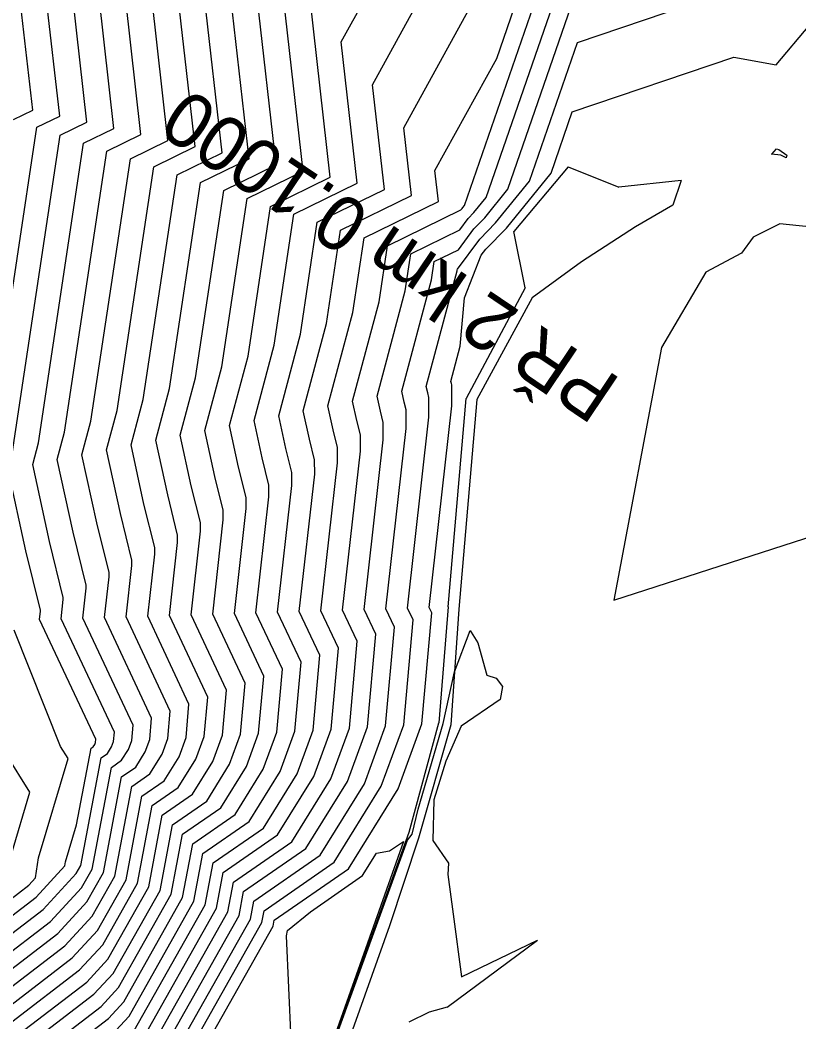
# Model space of a CAD drawing. Extents: x -549394 to -546608, y -1037055 to -1033629.
# Drawn here: x -547627.3 to -547498.3, y -1035691 to -1035525.2 of the extents above; entities that cross this region are included whole.
import ezdxf

# ---------------------------------------------------------------- set-up
doc = ezdxf.new("R2010")
doc.units = 0
for name, color, linetype in [('hlavni_vrst', 7, 'Continuous'), ('hrana_L', 7, 'Continuous'), ('norm_vrst', 7, 'Continuous'), ('x_popis_pricne_rezy_C11', 7, 'Continuous')]:
    doc.layers.add(name, color=color, linetype=linetype)

msp = doc.modelspace()

# ---------------------------------------------------------------- linework, layer by layer
at = {"layer": 'hlavni_vrst'}
for p, q in [((-547574.09, -1035528.75), (-547531.7, -1035451.74)), ((-547616.21, -1035542.07), (-547625.05, -1035464.23)), ((-547593.82, -1035547.12), (-547599.94, -1035493.2)), ((-547550.08, -1035554.5), (-547533.27, -1035505.92)), ((-547571.43, -1035552.17), (-547574.09, -1035528.75)), ((-547620.62, -1035544.22), (-547616.21, -1035542.07)), ((-547628.56, -1035596.95), (-547620.62, -1035544.22)), ((-547601.27, -1035550.76), (-547593.82, -1035547.12)), ((-547606.88, -1035587.96), (-547601.27, -1035550.76)), ((-547581.93, -1035557.29), (-547571.43, -1035552.17)), ((-547552.14, -1035557.03), (-547550.08, -1035554.5)), ((-547585.19, -1035578.97), (-547581.93, -1035557.29)), ((-547553.1, -1035558.01), (-547552.14, -1035557.03)), ((-547554.48, -1035559.88), (-547553.1, -1035558.01)), ((-547562.58, -1035563.83), (-547554.48, -1035559.88)), ((-547563.51, -1035569.98), (-547562.58, -1035563.83)), ((-547568.15, -1035587.41), (-547563.51, -1035569.98)), ((-547588.52, -1035591.45), (-547585.19, -1035578.97)), ((-547608.88, -1035595.49), (-547606.88, -1035587.96)), ((-547567.61, -1035589.92), (-547568.15, -1035587.41)), ((-547567.15, -1035591.76), (-547567.61, -1035589.92)), ((-547587.18, -1035597.62), (-547588.52, -1035591.45)), ((-547567.14, -1035594.65), (-547567.15, -1035591.76)), ((-547570.29, -1035622.71), (-547567.14, -1035594.65)), ((-547606.75, -1035605.31), (-547608.88, -1035595.49)), ((-547586.06, -1035602.12), (-547587.18, -1035597.62)), ((-547626.32, -1035613.01), (-547629.25, -1035599.53)), ((-547586.06, -1035604.1), (-547586.06, -1035602.12)), ((-547604.98, -1035612.47), (-547606.75, -1035605.31)), ((-547588.21, -1035623.26), (-547586.06, -1035604.1)), ((-547623.89, -1035622.83), (-547626.32, -1035613.01)), ((-547606.13, -1035623.81), (-547604.97, -1035613.54)), ((-547604.97, -1035613.54), (-547604.98, -1035612.47)), ((-547624.04, -1035624.36), (-547623.89, -1035622.98)), ((-547623.89, -1035622.98), (-547623.89, -1035622.83)), ((-547583.84, -1035632.6), (-547588.21, -1035623.26)), ((-547568.38, -1035626.79), (-547570.29, -1035622.71)), ((-547614.75, -1035644.21), (-547624.04, -1035624.36)), ((-547599.3, -1035638.4), (-547606.13, -1035623.81)), ((-547569.74, -1035642.17), (-547568.38, -1035626.79)), ((-547584.76, -1035643.03), (-547583.84, -1035632.6)), ((-547599.78, -1035643.89), (-547599.3, -1035638.4)), ((-547587, -1035649.14), (-547584.76, -1035643.03)), ((-547573.04, -1035651.17), (-547569.74, -1035642.17)), ((-547615.15, -1035645.45), (-547614.91, -1035645.06)), ((-547614.91, -1035645.06), (-547614.8, -1035644.75)), ((-547614.8, -1035644.75), (-547614.75, -1035644.21)), ((-547600.95, -1035647.1), (-547599.78, -1035643.89)), ((-547617.92, -1035658.38), (-547615.51, -1035645.69)), ((-547615.51, -1035645.69), (-547615.15, -1035645.45)), ((-547603.42, -1035651.06), (-547600.95, -1035647.1)), ((-547591.68, -1035656.67), (-547587, -1035649.14)), ((-547607.09, -1035653.6), (-547603.42, -1035651.06)), ((-547579.94, -1035662.28), (-547573.04, -1035651.17)), ((-547609.72, -1035667.46), (-547607.09, -1035653.6)), ((-547598.67, -1035661.51), (-547591.68, -1035656.67)), ((-547619.73, -1035664.49), (-547617.92, -1035658.38)), ((-547600.36, -1035670.41), (-547598.67, -1035661.51)), ((-547590.25, -1035669.42), (-547579.94, -1035662.28)), ((-547619.83, -1035665.15), (-547619.73, -1035664.49)), ((-547624.63, -1035670.35), (-547619.83, -1035665.15)), ((-547614.46, -1035675.87), (-547609.72, -1035667.46)), ((-547591, -1035673.37), (-547590.25, -1035669.42)), ((-547641.51, -1035683.3), (-547624.63, -1035670.35)), ((-547610.1, -1035687.67), (-547600.36, -1035670.41)), ((-547605.74, -1035699.48), (-547591, -1035673.37)), ((-547618.63, -1035680.39), (-547614.46, -1035675.87)), ((-547630.77, -1035689.69), (-547618.63, -1035680.39)), ((-547612.64, -1035690.42), (-547610.1, -1035687.67)), ((-547620.02, -1035696.08), (-547612.64, -1035690.42))]:
    msp.add_line(p, q, dxfattribs=at)
at = {"layer": 'hrana_L'}
for p, q in [((-547536.52, -1035549.43), (-547545.54, -1035560.15)), ((-547536.52, -1035549.43), (-547528.16, -1035552.81)), ((-547517.84, -1035551.7), (-547528.16, -1035552.81)), ((-547517.84, -1035551.7), (-547519.2, -1035555.78)), ((-547519.2, -1035555.78), (-547525.37, -1035559.4)), ((-547543.62, -1035569.46), (-547545.54, -1035560.15)), ((-547525.37, -1035559.4), (-547534.34, -1035565.16)), ((-547534.34, -1035565.16), (-547542.48, -1035571.14)), ((-547543.62, -1035569.46), (-547553.41, -1035587.8)), ((-547542.48, -1035571.14), (-547551.65, -1035587.97)), ((-547556.39, -1035622.28), (-547553.41, -1035587.8)), ((-547551.65, -1035587.97), (-547554.6, -1035622.69)), ((-547556.39, -1035622.28), (-547557.91, -1035641.49)), ((-547554.6, -1035622.69), (-547555.97, -1035641.83)), ((-547562.86, -1035659.58), (-547557.91, -1035641.49)), ((-547555.97, -1035641.83), (-547561.31, -1035660.56)), ((-547577.52, -1035700.25), (-547562.86, -1035659.58)), ((-547561.31, -1035660.56), (-547566.1, -1035675.11)), ((-547566.1, -1035675.11), (-547574.58, -1035698.92))]:
    msp.add_line(p, q, dxfattribs=at)
at = {"layer": 'norm_vrst'}
for p, q in [((-547611.73, -1035543.08), (-547620.63, -1035464.77)), ((-547607.25, -1035544.09), (-547615.45, -1035471.88)), ((-547620.69, -1035541.06), (-547628.31, -1035473.99)), ((-547568.92, -1035535.86), (-547534.38, -1035473.12)), ((-547602.78, -1035545.1), (-547610.28, -1035478.99)), ((-547625.17, -1035540.05), (-547631.56, -1035483.75)), ((-547548.36, -1035531.52), (-547531.56, -1035482.96)), ((-547598.3, -1035546.11), (-547605.11, -1035486.09)), ((-547553.66, -1035555.84), (-547532.42, -1035494.44)), ((-547589.34, -1035548.13), (-547594.77, -1035500.31)), ((-547563.74, -1035542.97), (-547541.37, -1035502.32)), ((-547584.86, -1035549.14), (-547589.6, -1035507.42)), ((-547580.38, -1035550.15), (-547584.43, -1035514.53)), ((-547546.5, -1035553.16), (-547534.13, -1035517.4)), ((-547534.99, -1035528.88), (-547500.11, -1035517.04)), ((-547575.91, -1035551.16), (-547579.26, -1035521.64)), ((-547502.11, -1035532.54), (-547496.51, -1035525.96)), ((-547542.92, -1035551.82), (-547534.99, -1035528.88)), ((-547558.57, -1035550.08), (-547548.36, -1035531.52)), ((-547535.84, -1035540.36), (-547509.07, -1035531.27)), ((-547509.07, -1035531.27), (-547502.11, -1035532.54)), ((-547566.95, -1035553.18), (-547568.92, -1035535.86)), ((-547628.35, -1035541.61), (-547625.17, -1035540.05)), ((-547539.35, -1035550.49), (-547535.84, -1035540.36)), ((-547624.49, -1035542.91), (-547620.69, -1035541.06)), ((-547632.9, -1035598.75), (-547624.49, -1035542.91)), ((-547616.75, -1035545.53), (-547611.73, -1035543.08)), ((-547562.47, -1035554.19), (-547563.74, -1035542.97)), ((-547624.22, -1035595.15), (-547616.75, -1035545.53)), ((-547612.88, -1035546.84), (-547607.25, -1035544.09)), ((-547609.01, -1035548.14), (-547602.78, -1035545.1)), ((-547619.89, -1035593.35), (-547612.88, -1035546.84)), ((-547605.14, -1035549.45), (-547598.3, -1035546.11)), ((-547502.83, -1035547.38), (-547502.79, -1035547.35)), ((-547502.79, -1035547.35), (-547502.01, -1035546.46)), ((-547502.01, -1035546.46), (-547501.63, -1035546.59)), ((-547501.63, -1035546.59), (-547500.34, -1035547.5)), ((-547615.55, -1035591.55), (-547609.01, -1035548.14)), ((-547597.4, -1035552.07), (-547589.34, -1035548.13)), ((-547501.29, -1035547.53), (-547502.83, -1035547.38)), ((-547500.43, -1035547.94), (-547501.29, -1035547.53)), ((-547500.34, -1035547.5), (-547500.43, -1035547.94)), ((-547611.21, -1035589.76), (-547605.14, -1035549.45)), ((-547593.53, -1035553.37), (-547584.86, -1035549.14)), ((-547589.66, -1035554.68), (-547580.38, -1035550.15)), ((-547557.99, -1035555.2), (-547558.57, -1035550.08)), ((-547546.75, -1035559.58), (-547539.35, -1035550.49)), ((-547602.54, -1035586.16), (-547597.4, -1035552.07)), ((-547585.8, -1035555.99), (-547575.91, -1035551.16)), ((-547548.54, -1035558.73), (-547542.92, -1035551.82)), ((-547598.2, -1035584.36), (-547593.53, -1035553.37)), ((-547578.06, -1035558.6), (-547566.95, -1035553.18)), ((-547550.34, -1035557.88), (-547546.5, -1035553.16)), ((-547593.87, -1035582.56), (-547589.66, -1035554.68)), ((-547574.19, -1035559.91), (-547562.47, -1035554.19)), ((-547570.32, -1035561.22), (-547557.99, -1035555.2)), ((-547589.53, -1035580.77), (-547585.8, -1035555.99)), ((-547566.45, -1035562.52), (-547554.27, -1035556.58)), ((-547554.27, -1035556.58), (-547554.07, -1035556.32)), ((-547554.07, -1035556.32), (-547553.94, -1035556.19)), ((-547553.94, -1035556.19), (-547553.66, -1035555.84)), ((-547580.85, -1035577.17), (-547578.06, -1035558.6)), ((-547552.13, -1035559.71), (-547550.34, -1035557.88)), ((-547551.16, -1035561.4), (-547548.54, -1035558.73)), ((-547501.49, -1035558.87), (-547505.88, -1035561.09)), ((-547492.29, -1035559.82), (-547501.49, -1035558.87)), ((-547576.52, -1035575.37), (-547574.19, -1035559.91)), ((-547554.7, -1035563.18), (-547552.13, -1035559.71)), ((-547550.18, -1035563.09), (-547546.75, -1035559.58)), ((-547572.18, -1035573.58), (-547570.32, -1035561.22)), ((-547554.84, -1035566.37), (-547551.16, -1035561.4)), ((-547505.88, -1035561.09), (-547507.85, -1035563.73)), ((-547567.84, -1035571.78), (-547566.45, -1035562.52)), ((-547558.71, -1035565.14), (-547554.7, -1035563.18)), ((-547550.9, -1035564.06), (-547550.18, -1035563.09)), ((-547507.85, -1035563.73), (-547513.72, -1035566.89)), ((-547559.17, -1035568.18), (-547558.71, -1035565.14)), ((-547553.7, -1035571.15), (-547550.9, -1035564.06)), ((-547560.01, -1035585.79), (-547554.91, -1035566.67)), ((-547554.91, -1035566.67), (-547554.9, -1035566.51)), ((-547554.9, -1035566.51), (-547554.84, -1035566.37)), ((-547513.72, -1035566.89), (-547521.05, -1035579.34)), ((-547564.08, -1035586.6), (-547559.17, -1035568.18)), ((-547572.22, -1035588.22), (-547567.84, -1035571.78)), ((-547554.38, -1035579.14), (-547553.7, -1035571.15)), ((-547576.3, -1035589.03), (-547572.18, -1035573.58)), ((-547580.37, -1035589.83), (-547576.52, -1035575.37)), ((-547584.44, -1035590.64), (-547580.85, -1035577.17)), ((-547555.93, -1035584.99), (-547554.38, -1035579.14)), ((-547521.05, -1035579.34), (-547528.95, -1035621.19)), ((-547592.59, -1035592.26), (-547589.53, -1035580.77)), ((-547596.66, -1035593.07), (-547593.87, -1035582.56)), ((-547600.74, -1035593.87), (-547598.2, -1035584.36)), ((-547555.86, -1035585.31), (-547555.93, -1035584.99)), ((-547555.8, -1035585.54), (-547555.86, -1035585.31)), ((-547604.81, -1035594.68), (-547602.54, -1035586.16)), ((-547563.69, -1035588.38), (-547564.08, -1035586.6)), ((-547559.78, -1035586.85), (-547560.01, -1035585.79)), ((-547559.59, -1035587.61), (-547559.78, -1035586.85)), ((-547555.79, -1035588.99), (-547555.8, -1035585.54)), ((-547571.52, -1035591.46), (-547572.22, -1035588.22)), ((-547563.37, -1035589.69), (-547563.69, -1035588.38)), ((-547559.58, -1035590.88), (-547559.59, -1035587.61)), ((-547612.96, -1035596.3), (-547611.21, -1035589.76)), ((-547579.35, -1035594.54), (-547580.37, -1035589.83)), ((-547575.43, -1035593), (-547576.3, -1035589.03)), ((-547563.36, -1035592.77), (-547563.37, -1035589.69)), ((-547559.54, -1035622.38), (-547555.79, -1035588.99)), ((-547617.03, -1035597.11), (-547615.55, -1035591.55)), ((-547583.26, -1035596.08), (-547584.44, -1035590.64)), ((-547570.93, -1035593.83), (-547571.52, -1035591.46)), ((-547563.13, -1035622.49), (-547559.58, -1035590.88)), ((-547621.1, -1035597.91), (-547619.89, -1035593.35)), ((-547595.01, -1035600.7), (-547596.66, -1035593.07)), ((-547591.09, -1035599.16), (-547592.59, -1035592.26)), ((-547574.72, -1035595.9), (-547575.43, -1035593)), ((-547566.71, -1035622.6), (-547563.36, -1035592.77)), ((-547625.18, -1035598.72), (-547624.22, -1035595.15)), ((-547602.83, -1035603.77), (-547604.81, -1035594.68)), ((-547598.92, -1035602.24), (-547600.74, -1035593.87)), ((-547578.5, -1035597.97), (-547579.35, -1035594.54)), ((-547570.93, -1035596.54), (-547570.93, -1035593.83)), ((-547614.58, -1035608.39), (-547617.03, -1035597.11)), ((-547610.66, -1035606.85), (-547612.96, -1035596.3)), ((-547582.28, -1035600.04), (-547583.26, -1035596.08)), ((-547574.71, -1035598.43), (-547574.72, -1035595.9)), ((-547573.88, -1035622.82), (-547570.93, -1035596.54)), ((-547622.41, -1035611.47), (-547625.18, -1035598.72)), ((-547618.49, -1035609.93), (-547621.1, -1035597.91)), ((-547578.49, -1035600.32), (-547578.5, -1035597.97)), ((-547577.46, -1035622.93), (-547574.71, -1035598.43)), ((-547589.85, -1035604.19), (-547591.09, -1035599.16)), ((-547582.28, -1035602.21), (-547582.28, -1035600.04)), ((-547581.04, -1035623.04), (-547578.49, -1035600.32)), ((-547593.63, -1035606.26), (-547595.01, -1035600.7)), ((-547597.41, -1035608.33), (-547598.92, -1035602.24)), ((-547584.63, -1035623.15), (-547582.28, -1035602.21)), ((-547601.19, -1035610.4), (-547602.83, -1035603.77)), ((-547589.84, -1035605.98), (-547589.85, -1035604.19)), ((-547608.76, -1035614.55), (-547610.66, -1035606.85)), ((-547593.62, -1035607.87), (-547593.63, -1035606.26)), ((-547591.79, -1035623.37), (-547589.84, -1035605.98)), ((-547612.54, -1035616.62), (-547614.58, -1035608.39)), ((-547597.41, -1035609.76), (-547597.41, -1035608.33)), ((-547595.38, -1035623.48), (-547593.62, -1035607.87)), ((-547616.32, -1035618.69), (-547618.49, -1035609.93)), ((-547598.96, -1035623.59), (-547597.41, -1035609.76)), ((-547620.11, -1035620.76), (-547622.41, -1035611.47)), ((-547602.54, -1035623.7), (-547601.19, -1035611.65)), ((-547601.19, -1035611.65), (-547601.19, -1035610.4)), ((-547528.95, -1035621.19), (-547495.64, -1035610.43)), ((-547608.76, -1035615.42), (-547608.76, -1035614.55)), ((-547612.54, -1035617.31), (-547612.54, -1035616.62)), ((-547609.71, -1035623.92), (-547608.76, -1035615.42)), ((-547613.29, -1035624.03), (-547612.54, -1035617.31)), ((-547616.88, -1035624.14), (-547616.32, -1035619.2)), ((-547616.32, -1035619.2), (-547616.32, -1035618.69)), ((-547620.46, -1035624.25), (-547620.11, -1035621.09)), ((-547620.11, -1035621.09), (-547620.11, -1035620.76)), ((-547593.11, -1035636.08), (-547598.96, -1035623.59)), ((-547590.02, -1035634.92), (-547595.38, -1035623.48)), ((-547586.93, -1035633.76), (-547591.79, -1035623.37)), ((-547580.75, -1035631.43), (-547584.63, -1035623.15)), ((-547577.66, -1035630.27), (-547581.04, -1035623.04)), ((-547574.57, -1035629.11), (-547577.46, -1035622.93)), ((-547571.47, -1035627.95), (-547573.88, -1035622.82)), ((-547565.29, -1035625.63), (-547566.71, -1035622.6)), ((-547562.2, -1035624.46), (-547563.13, -1035622.49)), ((-547560.73, -1035641.65), (-547559.11, -1035623.3)), ((-547559.11, -1035623.3), (-547559.54, -1035622.38)), ((-547611.66, -1035643.05), (-547620.46, -1035624.25)), ((-547608.57, -1035641.89), (-547616.88, -1035624.14)), ((-547605.48, -1035640.73), (-547613.29, -1035624.03)), ((-547602.39, -1035639.57), (-547609.71, -1035623.92)), ((-547596.2, -1035637.24), (-547602.54, -1035623.7)), ((-547563.74, -1035641.82), (-547562.2, -1035624.46)), ((-547620.57, -1035645.42), (-547628.26, -1035626.14)), ((-547566.74, -1035642), (-547565.29, -1035625.63)), ((-547555.34, -1035633.06), (-547552.77, -1035626.2)), ((-547552.77, -1035626.2), (-547552.59, -1035626.45)), ((-547552.59, -1035626.45), (-547551.46, -1035628.25)), ((-547572.75, -1035642.34), (-547571.47, -1035627.95)), ((-547551.46, -1035628.25), (-547550, -1035633.58)), ((-547578.75, -1035642.68), (-547577.66, -1035630.27)), ((-547575.75, -1035642.51), (-547574.57, -1035629.11)), ((-547581.76, -1035642.86), (-547580.75, -1035631.43)), ((-547557.23, -1035641.61), (-547555.34, -1035633.06)), ((-547550, -1035633.58), (-547548.47, -1035634.11)), ((-547590.77, -1035643.37), (-547590.02, -1035634.92)), ((-547587.77, -1035643.2), (-547586.93, -1035633.76)), ((-547548.47, -1035634.11), (-547547.38, -1035635.45)), ((-547593.77, -1035643.54), (-547593.11, -1035636.08)), ((-547547.38, -1035635.45), (-547547.79, -1035637.63)), ((-547596.78, -1035643.72), (-547596.2, -1035637.24)), ((-547547.79, -1035637.63), (-547554.25, -1035642.04)), ((-547602.78, -1035644.06), (-547602.39, -1035639.57)), ((-547608.79, -1035644.4), (-547608.57, -1035641.89)), ((-547605.79, -1035644.23), (-547605.48, -1035640.73)), ((-547567.46, -1035651.99), (-547563.74, -1035641.82)), ((-547564.66, -1035652.4), (-547560.73, -1035641.65)), ((-547561.38, -1035655.78), (-547557.23, -1035641.61)), ((-547611.79, -1035644.58), (-547611.66, -1035643.05)), ((-547595.37, -1035647.91), (-547593.77, -1035643.54)), ((-547592.58, -1035648.32), (-547590.77, -1035643.37)), ((-547589.79, -1035648.73), (-547587.77, -1035643.2)), ((-547584.21, -1035649.54), (-547581.76, -1035642.86)), ((-547581.41, -1035649.95), (-547578.75, -1035642.68)), ((-547578.62, -1035650.36), (-547575.75, -1035642.51)), ((-547575.83, -1035650.77), (-547572.75, -1035642.34)), ((-547570.25, -1035651.58), (-547566.74, -1035642)), ((-547554.25, -1035642.04), (-547556.76, -1035647.82)), ((-547612.12, -1035645.47), (-547611.79, -1035644.58)), ((-547609.33, -1035645.88), (-547608.79, -1035644.4)), ((-547606.54, -1035646.28), (-547605.79, -1035644.23)), ((-547603.75, -1035646.69), (-547602.78, -1035644.06)), ((-547598.16, -1035647.51), (-547596.78, -1035643.72)), ((-547625.63, -1035652.96), (-547629.59, -1035646.68)), ((-547619.32, -1035647.4), (-547620.57, -1035645.42)), ((-547613.83, -1035647.28), (-547612.81, -1035646.57)), ((-547612.81, -1035646.57), (-547612.12, -1035645.47)), ((-547610.46, -1035647.69), (-547609.33, -1035645.88)), ((-547608.11, -1035648.81), (-547606.54, -1035646.28)), ((-547605.76, -1035649.94), (-547603.75, -1035646.69)), ((-547624.19, -1035663.84), (-547619.32, -1035647.4)), ((-547617.21, -1035665.09), (-547613.83, -1035647.28)), ((-547612.14, -1035648.86), (-547610.46, -1035647.69)), ((-547601.07, -1035652.18), (-547598.16, -1035647.51)), ((-547598.72, -1035653.3), (-547595.37, -1035647.91)), ((-547596.37, -1035654.43), (-547592.58, -1035648.32)), ((-547556.76, -1035647.82), (-547558.75, -1035654.22)), ((-547615.33, -1035665.68), (-547612.14, -1035648.86)), ((-547610.46, -1035650.44), (-547608.11, -1035648.81)), ((-547608.78, -1035652.02), (-547605.76, -1035649.94)), ((-547594.03, -1035655.55), (-547589.79, -1035648.73)), ((-547589.33, -1035657.79), (-547584.21, -1035649.54)), ((-547586.98, -1035658.92), (-547581.41, -1035649.95)), ((-547613.46, -1035666.28), (-547610.46, -1035650.44)), ((-547584.64, -1035660.04), (-547578.62, -1035650.36)), ((-547582.29, -1035661.16), (-547575.83, -1035650.77)), ((-547577.6, -1035663.41), (-547570.25, -1035651.58)), ((-547628.66, -1035663.2), (-547625.63, -1035652.96)), ((-547611.59, -1035666.87), (-547608.78, -1035652.02)), ((-547605.41, -1035655.19), (-547601.07, -1035652.18)), ((-547603.72, -1035656.77), (-547598.72, -1035653.3)), ((-547575.25, -1035664.53), (-547567.46, -1035651.99)), ((-547572.9, -1035665.65), (-547564.66, -1035652.4)), ((-547602.04, -1035658.35), (-547596.37, -1035654.43)), ((-547558.75, -1035654.22), (-547558.93, -1035660.97)), ((-547607.85, -1035668.05), (-547605.41, -1035655.19)), ((-547605.97, -1035668.64), (-547603.72, -1035656.77)), ((-547600.36, -1035659.93), (-547594.03, -1035655.55)), ((-547562.34, -1035659.91), (-547561.38, -1035655.78)), ((-547604.1, -1035669.23), (-547602.04, -1035658.35)), ((-547596.99, -1035663.1), (-547589.33, -1035657.79)), ((-547602.23, -1035669.82), (-547600.36, -1035659.93)), ((-547595.3, -1035664.68), (-547586.98, -1035658.92)), ((-547593.62, -1035666.26), (-547584.64, -1035660.04)), ((-547563.14, -1035660.91), (-547562.34, -1035659.91)), ((-547591.94, -1035667.84), (-547582.29, -1035661.16)), ((-547563.76, -1035661.11), (-547577.42, -1035699.63)), ((-547577.17, -1035699.49), (-547563.14, -1035660.91)), ((-547566.12, -1035662.68), (-547563.76, -1035661.11)), ((-547558.93, -1035660.97), (-547556.31, -1035664.7)), ((-547598.49, -1035671), (-547596.99, -1035663.1)), ((-547588.57, -1035671.01), (-547577.6, -1035663.41)), ((-547570.55, -1035666.78), (-547568.25, -1035663.07)), ((-547568.25, -1035663.07), (-547566.12, -1035662.68)), ((-547624.72, -1035667.14), (-547624.19, -1035663.84)), ((-547617.96, -1035666.42), (-547617.21, -1035665.09)), ((-547596.62, -1035671.59), (-547595.3, -1035664.68)), ((-547586.88, -1035672.59), (-547575.25, -1035664.53)), ((-547556.31, -1035664.7), (-547556.47, -1035666.61)), ((-547623.43, -1035672.36), (-547617.96, -1035666.42)), ((-547617.08, -1035668.78), (-547615.33, -1035665.68)), ((-547616.21, -1035671.14), (-547613.46, -1035666.28)), ((-547594.74, -1035672.19), (-547593.62, -1035666.26)), ((-547585.2, -1035674.17), (-547572.9, -1035665.65)), ((-547556.47, -1035666.61), (-547555.56, -1035673.17)), ((-547643.66, -1035682.02), (-547625.83, -1035668.34)), ((-547625.83, -1035668.34), (-547624.72, -1035667.14)), ((-547615.34, -1035673.5), (-547611.59, -1035666.87)), ((-547613.59, -1035678.23), (-547607.85, -1035668.05)), ((-547592.87, -1035672.78), (-547591.94, -1035667.84)), ((-547579.19, -1035672.75), (-547570.55, -1035666.78)), ((-547622.23, -1035674.36), (-547617.08, -1035668.78)), ((-547612.72, -1035680.59), (-547605.97, -1035668.64)), ((-547611.85, -1035682.95), (-547604.1, -1035669.23)), ((-547610.97, -1035685.31), (-547602.23, -1035669.82)), ((-547621.03, -1035676.37), (-547616.21, -1035671.14)), ((-547609.23, -1035690.03), (-547598.49, -1035671)), ((-547608.36, -1035692.4), (-547596.62, -1035671.59)), ((-547589.13, -1035673.96), (-547588.57, -1035671.01)), ((-547639.37, -1035684.58), (-547623.43, -1035672.36)), ((-547607.48, -1035694.76), (-547594.74, -1035672.19)), ((-547606.61, -1035697.12), (-547592.87, -1035672.78)), ((-547587.26, -1035674.55), (-547586.88, -1035672.59)), ((-547583.01, -1035675.87), (-547579.19, -1035672.75)), ((-547555.56, -1035673.17), (-547554.16, -1035683.55)), ((-547637.22, -1035685.85), (-547622.23, -1035674.36)), ((-547619.83, -1035678.38), (-547615.34, -1035673.5)), ((-547604.86, -1035701.84), (-547589.13, -1035673.96)), ((-547603.99, -1035704.2), (-547587.26, -1035674.55)), ((-547585.38, -1035675.14), (-547585.2, -1035674.17)), ((-547635.07, -1035687.13), (-547621.03, -1035676.37)), ((-547599.56, -1035700.26), (-547585.38, -1035675.14)), ((-547583.15, -1035676.75), (-547583.01, -1035675.87)), ((-547632.92, -1035688.41), (-547619.83, -1035678.38)), ((-547617.44, -1035682.39), (-547613.59, -1035678.23)), ((-547582.36, -1035693.94), (-547583.15, -1035676.75)), ((-547556.55, -1035688.55), (-547541.61, -1035677.48)), ((-547554.16, -1035683.55), (-547541.61, -1035677.48)), ((-547616.24, -1035684.4), (-547612.72, -1035680.59)), ((-547628.62, -1035690.97), (-547617.44, -1035682.39)), ((-547615.04, -1035686.41), (-547611.85, -1035682.95)), ((-547626.47, -1035692.25), (-547616.24, -1035684.4)), ((-547624.32, -1035693.53), (-547615.04, -1035686.41)), ((-547613.84, -1035688.42), (-547610.97, -1035685.31)), ((-547622.17, -1035694.81), (-547613.84, -1035688.42)), ((-547559.53, -1035689.37), (-547562.91, -1035691.03)), ((-547556.55, -1035688.55), (-547559.53, -1035689.37)), ((-547611.44, -1035692.43), (-547609.23, -1035690.03))]:
    msp.add_line(p, q, dxfattribs=at)

# ---------------------------------------------------------------- texts
at = {"layer": 'x_popis_pricne_rezy_C11'}
msp.add_text('PŘ 2 km 0.1000', height=9.0627, rotation=146.0236, dxfattribs=at).set_placement((-547527.52, -1035584.75))

doc.saveas('drawing.dxf')
